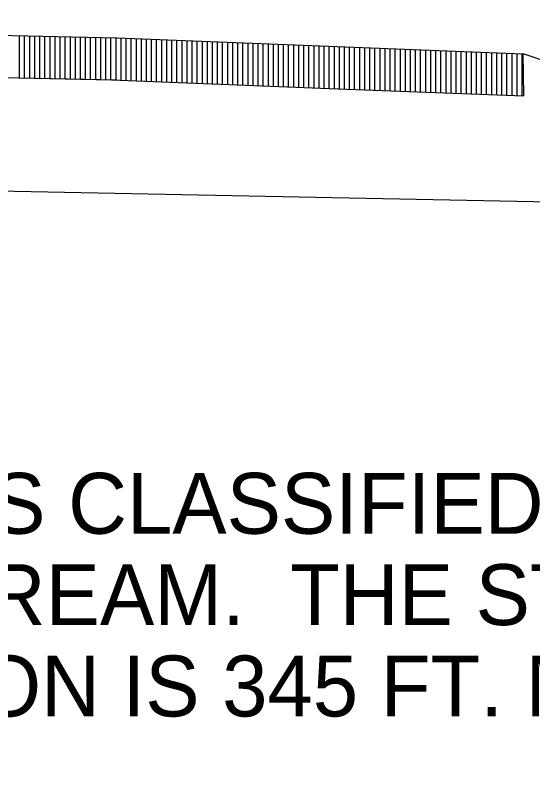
# Model space of a CAD drawing. Extents: x 3575 to 11445, y 9479 to 13278.
# Drawn here: x 7094.7 to 7145.7, y 10417.2 to 10492.8 of the extents above; entities that cross this region are included whole.
import ezdxf

# ---------------------------------------------------------------- set-up
doc = ezdxf.new("R2010")
doc.units = 0
for name, color, linetype in [('ACHM Surface', 7, 'Continuous'), ('Default', 7, 'Continuous'), ('Pavement Layers', 7, 'Continuous'), ('STAMP_PE_CRAFTON-SIGNATURE', 7, 'Continuous')]:
    doc.layers.add(name, color=color, linetype=linetype)

msp = doc.modelspace()

# ---------------------------------------------------------------- linework, layer by layer
at = {"layer": 'ACHM Surface'}
for p, q in [((7095.139, 10486.598), (7095.139, 10490.766)), ((7095.639, 10486.589), (7095.639, 10490.756)), ((7096.139, 10486.579), (7096.139, 10490.746)), ((7096.639, 10486.569), (7096.639, 10490.736)), ((7097.139, 10486.56), (7097.139, 10490.726)), ((7097.639, 10486.55), (7097.639, 10490.716)), ((7098.139, 10486.54), (7098.139, 10490.706)), ((7098.639, 10486.53), (7098.639, 10490.696)), ((7099.139, 10486.521), (7099.139, 10490.686)), ((7099.639, 10486.511), (7099.639, 10490.676)), ((7100.139, 10486.501), (7100.139, 10490.666)), ((7100.639, 10486.491), (7100.639, 10490.656)), ((7101.139, 10486.482), (7101.139, 10490.646)), ((7101.639, 10486.472), (7101.639, 10490.636)), ((7102.139, 10486.462), (7102.139, 10490.626)), ((7102.639, 10486.452), (7102.639, 10490.616)), ((7103.139, 10486.443), (7103.139, 10490.606)), ((7103.639, 10486.433), (7103.639, 10490.596)), ((7104.139, 10486.423), (7104.139, 10490.586)), ((7104.639, 10486.408), (7104.639, 10490.576)), ((7105.139, 10486.391), (7105.139, 10490.558)), ((7105.639, 10486.371), (7105.639, 10490.538)), ((7106.139, 10486.351), (7106.139, 10490.518)), ((7106.639, 10486.332), (7106.639, 10490.498)), ((7107.139, 10486.312), (7107.139, 10490.478)), ((7107.639, 10486.293), (7107.639, 10490.458)), ((7108.139, 10486.273), (7108.139, 10490.438)), ((7108.639, 10486.254), (7108.639, 10490.418)), ((7109.139, 10486.234), (7109.139, 10490.398)), ((7109.639, 10486.215), (7109.639, 10490.378)), ((7110.139, 10486.195), (7110.139, 10490.358)), ((7110.639, 10486.176), (7110.639, 10490.338)), ((7111.139, 10486.156), (7111.139, 10490.318)), ((7111.639, 10486.136), (7111.639, 10490.298)), ((7112.139, 10486.117), (7112.139, 10490.278)), ((7112.639, 10486.097), (7112.639, 10490.258)), ((7113.139, 10486.078), (7113.139, 10490.238)), ((7113.639, 10486.058), (7113.639, 10490.218)), ((7114.139, 10486.039), (7114.139, 10490.198)), ((7114.639, 10486.019), (7114.639, 10490.178)), ((7115.139, 10486), (7115.139, 10490.158)), ((7115.639, 10485.98), (7115.639, 10490.138)), ((7116.139, 10485.961), (7116.139, 10490.118)), ((7116.639, 10485.941), (7116.639, 10490.098)), ((7117.139, 10485.921), (7117.139, 10490.078)), ((7117.639, 10485.902), (7117.639, 10490.058)), ((7118.139, 10485.882), (7118.139, 10490.038)), ((7118.639, 10485.863), (7118.639, 10490.018)), ((7119.139, 10485.843), (7119.139, 10489.998)), ((7119.639, 10485.824), (7119.639, 10489.978)), ((7120.139, 10485.804), (7120.139, 10489.958)), ((7120.639, 10485.785), (7120.639, 10489.938)), ((7121.139, 10485.765), (7121.139, 10489.918)), ((7121.639, 10485.745), (7121.639, 10489.898)), ((7122.139, 10485.726), (7122.139, 10489.878)), ((7122.639, 10485.706), (7122.639, 10489.858)), ((7123.139, 10485.687), (7123.139, 10489.838)), ((7123.639, 10485.667), (7123.639, 10489.818)), ((7124.139, 10485.648), (7124.139, 10489.798)), ((7124.639, 10485.628), (7124.639, 10489.778)), ((7125.139, 10485.609), (7125.139, 10489.758)), ((7125.639, 10485.589), (7125.639, 10489.738)), ((7126.139, 10485.57), (7126.139, 10489.718)), ((7126.639, 10485.55), (7126.639, 10489.698)), ((7127.139, 10485.53), (7127.139, 10489.678)), ((7127.639, 10485.511), (7127.639, 10489.658)), ((7128.139, 10485.491), (7128.139, 10489.638)), ((7128.639, 10485.472), (7128.639, 10489.618)), ((7129.139, 10485.452), (7129.139, 10489.598)), ((7129.639, 10485.433), (7129.639, 10489.578)), ((7130.139, 10485.413), (7130.139, 10489.558)), ((7130.639, 10485.394), (7130.639, 10489.538)), ((7131.139, 10485.374), (7131.139, 10489.518)), ((7131.639, 10485.354), (7131.639, 10489.498)), ((7132.139, 10485.335), (7132.139, 10489.478)), ((7132.639, 10485.315), (7132.639, 10489.458)), ((7133.139, 10485.296), (7133.139, 10489.438)), ((7133.639, 10485.276), (7133.639, 10489.418)), ((7134.139, 10485.257), (7134.139, 10489.398)), ((7134.639, 10485.237), (7134.639, 10489.378)), ((7135.139, 10485.218), (7135.139, 10489.358)), ((7135.639, 10485.198), (7135.639, 10489.338)), ((7136.139, 10485.179), (7136.139, 10489.318)), ((7136.639, 10485.159), (7136.639, 10489.298)), ((7137.139, 10485.139), (7137.139, 10489.278)), ((7137.639, 10485.12), (7137.639, 10489.258)), ((7138.139, 10485.1), (7138.139, 10489.238)), ((7138.639, 10485.081), (7138.639, 10489.218)), ((7139.139, 10485.061), (7139.139, 10489.198)), ((7139.639, 10485.042), (7139.639, 10489.178)), ((7140.139, 10485.022), (7140.139, 10489.158)), ((7140.639, 10485.003), (7140.639, 10489.138)), ((7141.139, 10484.983), (7141.139, 10489.118)), ((7141.639, 10484.964), (7141.639, 10489.098)), ((7142.139, 10484.944), (7142.139, 10489.078)), ((7142.639, 10484.924), (7142.639, 10489.058)), ((7143.139, 10484.905), (7143.139, 10489.038)), ((7143.639, 10484.885), (7143.639, 10489.018)), ((7144.139, 10484.866), (7144.139, 10488.998)), ((7144.639, 10484.846), (7144.639, 10488.978))]:
    msp.add_line(p, q, dxfattribs=at)
at = {"layer": 'Default'}
for p, q in [((6994.783, 10492.773), (7104.761, 10490.573)), ((7104.761, 10490.573), (7144.729, 10488.975)), ((7144.808, 10484.84), (7144.729, 10488.975)), ((7360.169, 10417.162), (7144.729, 10488.975)), ((6994.567, 10477.441), (7191.124, 10473.51))]:
    msp.add_line(p, q, dxfattribs=at)
msp.add_lwpolyline([(6994.75, 10488.606), (7095.051, 10486.6), (7104.192, 10486.422), (7125.63, 10485.571), (7144.808, 10484.84)], dxfattribs=at)
at = {"layer": 'Pavement Layers'}
msp.add_line((7095.051, 10486.6), (7104.728, 10486.407), dxfattribs=at)

# ---------------------------------------------------------------- texts
at = {"layer": 'STAMP_PE_CRAFTON-SIGNATURE'}
for s, p in [('THIS STREAM IS CLASSIFIED AS A ', (7033.945, 10441.686)), ('PERENNIAL STREAM.  THE STREAM ', (7033.945, 10432.686)), ('BANK ELEVATION IS 345 FT. MSL.', (7033.945, 10423.686))]:
    msp.add_text(s, height=6, dxfattribs=at).set_placement(p)

doc.saveas('drawing.dxf')
